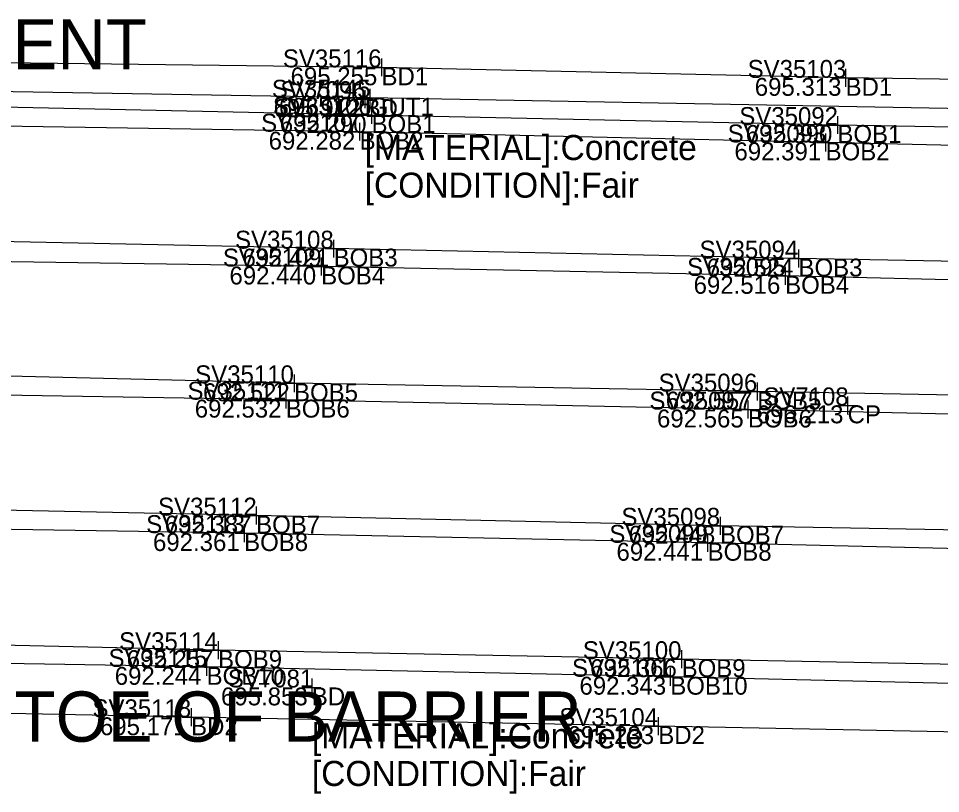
# Model space of a CAD drawing. Extents: x 1660019 to 1662995, y 619975 to 620342.
# Drawn here: x 1661296.6 to 1661348, y 620210.2 to 620253.4 of the extents above; entities that cross this region are included whole.
import ezdxf

# ---------------------------------------------------------------- set-up
doc = ezdxf.new("R2010")
doc.units = 0
for name, color, linetype in [('BR_X_Rail_Object', 7, 'Continuous'), ('BR_X_SV_Bottom_of_Beam', 7, 'Continuous'), ('BR_X_SV_Bottom_of_Beam_Text', 7, 'Continuous'), ('BR_X_SV_Deck_Top', 7, 'Continuous'), ('BR_X_SV_Deck_Top_Text', 7, 'Continuous'), ('PV_X_Curb', 7, 'Continuous'), ('RD_P_GR_Lt', 7, 'Continuous'), ('RD_X_GR_Bar', 7, 'Continuous'), ('RD_X_Wall', 7, 'Continuous'), ('SC_Scratch6', 7, 'Continuous'), ('SV_X_Text', 7, 'Continuous')]:
    doc.layers.add(name, color=color, linetype=linetype)

msp = doc.modelspace()

# ---------------------------------------------------------------- linework, layer by layer
at = {"layer": 'BR_X_SV_Bottom_of_Beam'}
for points in [[(1661523.404, 620243.849), (1661497.415, 620244.383), (1661471.694, 620244.95), (1661445.773, 620245.45), (1661419.903, 620245.974), (1661394.009, 620246.51), (1661368.147, 620247.032), (1661342.287, 620247.488), (1661316.311, 620248.045), (1661290.557, 620248.602), (1661264.648, 620249.031), (1661238.6, 620249.579)], [(1661517.582, 620243.008), (1661496.897, 620243.44), (1661470.919, 620243.838), (1661445.09, 620244.441), (1661419.147, 620244.946), (1661393.26, 620245.417), (1661367.358, 620245.921), (1661341.629, 620246.518), (1661315.646, 620247.115), (1661289.746, 620247.518), (1661264.383, 620248.322), (1661238.204, 620248.614)], [(1661521.265, 620236.365), (1661495.332, 620236.959), (1661469.491, 620237.512), (1661443.572, 620237.996), (1661417.708, 620238.508), (1661391.884, 620239.08), (1661365.994, 620239.561), (1661340.119, 620240.034), (1661314.197, 620240.589), (1661288.354, 620241.145), (1661262.476, 620241.611), (1661236.623, 620242.15)], [(1661520.605, 620235.452), (1661494.63, 620235.975), (1661468.71, 620236.383), (1661442.944, 620236.996), (1661417.103, 620237.514), (1661391.103, 620237.982), (1661365.202, 620238.448), (1661339.374, 620239.07), (1661313.502, 620239.591), (1661287.59, 620239.99), (1661261.723, 620240.632), (1661235.908, 620241.144)], [(1661519.081, 620228.953), (1661493.234, 620229.438), (1661467.368, 620230.031), (1661441.422, 620230.57), (1661415.6, 620231.071), (1661389.731, 620231.651), (1661363.823, 620232.132), (1661337.817, 620232.613), (1661311.988, 620233.076), (1661286.183, 620233.721), (1661260.328, 620234.129), (1661234.382, 620234.656)], [(1661518.51, 620227.977), (1661492.527, 620228.475), (1661466.56, 620228.954), (1661440.742, 620229.56), (1661414.823, 620230.069), (1661388.938, 620230.522), (1661363.07, 620231.021), (1661337.298, 620231.612), (1661311.527, 620232.162), (1661285.446, 620232.587), (1661259.588, 620233.138), (1661233.669, 620233.674)], [(1661516.938, 620221.488), (1661491.079, 620222.019), (1661465.187, 620222.58), (1661439.251, 620223.092), (1661413.441, 620223.61), (1661387.584, 620224.174), (1661361.703, 620224.657), (1661335.742, 620225.126), (1661309.876, 620225.693), (1661284.015, 620226.238), (1661258.155, 620226.696), (1661232.1, 620227.235)], [(1661516.255, 620220.542), (1661490.624, 620220.907), (1661464.53, 620221.454), (1661438.64, 620222.101), (1661412.707, 620222.613), (1661386.76, 620223.066), (1661360.949, 620223.557), (1661335.05, 620224.176), (1661309.206, 620224.717), (1661283.267, 620225.126), (1661257.537, 620225.694), (1661231.605, 620226.262)], [(1661514.756, 620214.059), (1661488.914, 620214.555), (1661463.017, 620215.148), (1661437.126, 620215.616), (1661411.256, 620216.167), (1661385.428, 620216.691), (1661359.541, 620217.184), (1661333.602, 620217.682), (1661307.754, 620218.183), (1661281.891, 620218.773), (1661255.858, 620219.275), (1661229.67, 620219.799)], [(1661514.073, 620213.08), (1661488.21, 620213.597), (1661462.263, 620214.044), (1661436.515, 620214.643), (1661410.516, 620215.165), (1661384.602, 620215.601), (1661358.815, 620216.084), (1661332.968, 620216.701), (1661307.113, 620217.251), (1661281.101, 620217.691), (1661255.319, 620218.266), (1661229.464, 620218.851)]]:
    msp.add_lwpolyline(points, dxfattribs=at)
at = {"layer": 'BR_X_SV_Deck_Top'}
for points in [[(1661524.154, 620246.519), (1661498.291, 620247.067), (1661472.426, 620247.598), (1661446.524, 620248.074), (1661420.55, 620248.604), (1661394.772, 620249.021), (1661368.927, 620249.743), (1661342.743, 620250.117), (1661316.866, 620250.706), (1661291.246, 620251.013), (1661265.132, 620251.796)], [(1661513.529, 620210.295), (1661487.664, 620211.099), (1661461.66, 620211.354), (1661435.632, 620211.885), (1661409.962, 620212.424), (1661383.838, 620212.928), (1661332.298, 620213.947), (1661306.248, 620214.439), (1661280.429, 620214.969), (1661254.732, 620215.771)]]:
    msp.add_lwpolyline(points, dxfattribs=at)
at = {"layer": 'PV_X_Curb'}
msp.add_lwpolyline([(1661523.342, 620245.121), (1661471.566, 620246.113), (1661445.996, 620246.597), (1661316.22, 620249.01), (1661290.79, 620249.439), (1661264.952, 620250.247), (1661238.714, 620250.79)], dxfattribs=at)
at = {"layer": 'RD_P_GR_Lt'}
for p, q in [((1661316.866, 620251.206), (1661316.866, 620250.206)), ((1661316.366, 620250.706), (1661317.366, 620250.706)), ((1661316.866, 620250.706), (1661316.866, 620250.706)), ((1661342.743, 620250.617), (1661342.743, 620249.617)), ((1661342.243, 620250.117), (1661343.243, 620250.117)), ((1661342.743, 620250.117), (1661342.743, 620250.117)), ((1661315.927, 620249.432), (1661315.927, 620248.432)), ((1661316.22, 620249.51), (1661316.22, 620248.51)), ((1661315.427, 620248.932), (1661316.427, 620248.932)), ((1661315.72, 620249.01), (1661316.72, 620249.01)), ((1661315.927, 620248.932), (1661315.927, 620248.932)), ((1661316.22, 620249.01), (1661316.22, 620249.01)), ((1661316.311, 620248.545), (1661316.311, 620247.545)), ((1661315.811, 620248.045), (1661316.811, 620248.045)), ((1661316.311, 620248.045), (1661316.311, 620248.045)), ((1661342.287, 620247.988), (1661342.287, 620246.988)), ((1661315.646, 620247.615), (1661315.646, 620246.615)), ((1661341.787, 620247.488), (1661342.787, 620247.488)), ((1661342.287, 620247.488), (1661342.287, 620247.488)), ((1661315.146, 620247.115), (1661316.146, 620247.115)), ((1661315.646, 620247.115), (1661315.646, 620247.115)), ((1661341.629, 620247.018), (1661341.629, 620246.018)), ((1661341.129, 620246.518), (1661342.129, 620246.518)), ((1661341.629, 620246.518), (1661341.629, 620246.518)), ((1661314.197, 620241.089), (1661314.197, 620240.089)), ((1661313.697, 620240.589), (1661314.697, 620240.589)), ((1661314.197, 620240.589), (1661314.197, 620240.589)), ((1661340.119, 620240.534), (1661340.119, 620239.534)), ((1661313.502, 620240.091), (1661313.502, 620239.091)), ((1661339.619, 620240.034), (1661340.619, 620240.034)), ((1661340.119, 620240.034), (1661340.119, 620240.034)), ((1661313.002, 620239.591), (1661314.002, 620239.591)), ((1661313.502, 620239.591), (1661313.502, 620239.591)), ((1661339.374, 620239.57), (1661339.374, 620238.57)), ((1661338.874, 620239.07), (1661339.874, 620239.07)), ((1661339.374, 620239.07), (1661339.374, 620239.07)), ((1661311.988, 620233.576), (1661311.988, 620232.576)), ((1661311.488, 620233.076), (1661312.488, 620233.076)), ((1661311.988, 620233.076), (1661311.988, 620233.076)), ((1661337.817, 620233.113), (1661337.817, 620232.113)), ((1661311.527, 620232.662), (1661311.527, 620231.662)), ((1661337.317, 620232.613), (1661338.317, 620232.613)), ((1661337.817, 620232.613), (1661337.817, 620232.613)), ((1661311.027, 620232.162), (1661312.027, 620232.162)), ((1661311.527, 620232.162), (1661311.527, 620232.162)), ((1661337.298, 620232.112), (1661337.298, 620231.112)), ((1661342.854, 620232.344), (1661342.854, 620231.344)), ((1661336.798, 620231.612), (1661337.798, 620231.612)), ((1661337.298, 620231.612), (1661337.298, 620231.612)), ((1661342.354, 620231.844), (1661343.354, 620231.844)), ((1661342.854, 620231.844), (1661342.854, 620231.844)), ((1661309.876, 620226.193), (1661309.876, 620225.193)), ((1661309.376, 620225.693), (1661310.376, 620225.693)), ((1661309.876, 620225.693), (1661309.876, 620225.693)), ((1661335.742, 620225.626), (1661335.742, 620224.626)), ((1661308.706, 620224.717), (1661309.706, 620224.717)), ((1661309.206, 620225.217), (1661309.206, 620224.217)), ((1661309.206, 620224.717), (1661309.206, 620224.717)), ((1661335.242, 620225.126), (1661336.242, 620225.126)), ((1661335.742, 620225.126), (1661335.742, 620225.126)), ((1661335.05, 620224.676), (1661335.05, 620223.676)), ((1661334.55, 620224.176), (1661335.55, 620224.176)), ((1661335.05, 620224.176), (1661335.05, 620224.176)), ((1661307.754, 620218.683), (1661307.754, 620217.683)), ((1661307.254, 620218.183), (1661308.254, 620218.183)), ((1661307.754, 620218.183), (1661307.754, 620218.183)), ((1661333.602, 620218.182), (1661333.602, 620217.182)), ((1661307.113, 620217.751), (1661307.113, 620216.751)), ((1661333.102, 620217.682), (1661334.102, 620217.682)), ((1661333.602, 620217.682), (1661333.602, 620217.682)), ((1661306.613, 620217.251), (1661307.613, 620217.251)), ((1661307.113, 620217.251), (1661307.113, 620217.251)), ((1661332.968, 620217.201), (1661332.968, 620216.201)), ((1661312.981, 620216.605), (1661312.981, 620215.605)), ((1661332.468, 620216.701), (1661333.468, 620216.701)), ((1661332.968, 620216.701), (1661332.968, 620216.701)), ((1661312.481, 620216.105), (1661313.481, 620216.105)), ((1661312.981, 620216.105), (1661312.981, 620216.105)), ((1661306.248, 620214.939), (1661306.248, 620213.939)), ((1661305.748, 620214.439), (1661306.748, 620214.439)), ((1661306.248, 620214.439), (1661306.248, 620214.439)), ((1661332.298, 620214.447), (1661332.298, 620213.447)), ((1661331.798, 620213.947), (1661332.798, 620213.947)), ((1661332.298, 620213.947), (1661332.298, 620213.947))]:
    msp.add_line(p, q, dxfattribs=at)

# ---------------------------------------------------------------- texts
at = {"layer": 'BR_X_Rail_Object'}
for s, p in [('GUT1', (1661316.22, 620248.01)), ('CP', (1661342.854, 620230.844))]:
    msp.add_text(s, height=1, dxfattribs=at).set_placement(p)
at = {"layer": 'BR_X_SV_Bottom_of_Beam_Text'}
for s, p in [('SV35106', (1661310.811, 620248.045)), ('SV35092', (1661336.818, 620247.488)), ('SV35107', (1661310.154, 620247.115)), ('692.290', (1661311.197, 620247.045)), ('BOB1', (1661316.311, 620247.045)), ('SV35093', (1661336.169, 620246.518)), ('692.390', (1661337.173, 620246.488)), ('BOB1', (1661342.287, 620246.488)), ('692.282', (1661310.573, 620246.115)), ('BOB2', (1661315.646, 620246.115)), ('692.391', (1661336.547, 620245.518)), ('BOB2', (1661341.629, 620245.518)), ('SV35108', (1661308.7, 620240.589)), ('SV35094', (1661334.601, 620240.034)), ('SV35109', (1661308.022, 620239.591)), ('692.421', (1661309.115, 620239.589)), ('BOB3', (1661314.197, 620239.589)), ('SV35095', (1661333.907, 620239.07)), ('692.524', (1661334.997, 620239.034)), ('BOB3', (1661340.119, 620239.034)), ('692.440', (1661308.388, 620238.591)), ('BOB4', (1661313.502, 620238.591)), ('692.516', (1661334.27, 620238.07)), ('BOB4', (1661339.374, 620238.07)), ('SV35110', (1661306.478, 620233.076)), ('SV35096', (1661332.317, 620232.613)), ('SV35111', (1661306.049, 620232.162)), ('692.522', (1661306.915, 620232.076)), ('BOB5', (1661311.988, 620232.076)), ('SV35097', (1661331.806, 620231.612)), ('692.557', (1661332.721, 620231.613)), ('BOB5', (1661337.817, 620231.613)), ('692.532', (1661306.454, 620231.162)), ('BOB6', (1661311.527, 620231.162)), ('692.565', (1661332.228, 620230.612)), ('BOB6', (1661337.298, 620230.612)), ('SV35112', (1661304.407, 620225.693)), ('SV35098', (1661330.245, 620225.126)), ('SV35113', (1661303.746, 620224.717)), ('692.387', (1661304.78, 620224.693)), ('BOB7', (1661309.876, 620224.693)), ('692.361', (1661304.124, 620223.717)), ('BOB8', (1661309.206, 620223.717)), ('SV35099', (1661329.57, 620224.176)), ('692.448', (1661330.642, 620224.126)), ('BOB7', (1661335.742, 620224.126)), ('692.441', (1661329.968, 620223.176)), ('BOB8', (1661335.05, 620223.176)), ('SV35114', (1661302.236, 620218.183)), ('SV35100', (1661328.092, 620217.682)), ('SV35115', (1661301.646, 620217.251)), ('692.257', (1661302.658, 620217.183)), ('BOB9', (1661307.754, 620217.183)), ('SV35101', (1661327.49, 620216.701)), ('692.366', (1661328.498, 620216.682)), ('BOB9', (1661333.602, 620216.682)), ('692.244', (1661301.991, 620216.251)), ('BOB10', (1661307.113, 620216.251)), ('692.343', (1661327.904, 620215.701)), ('BOB10', (1661332.968, 620215.701))]:
    msp.add_text(s, height=1, dxfattribs=at).set_placement(p)
at = {"layer": 'BR_X_SV_Deck_Top_Text'}
for s, p in [('SV35116', (1661311.366, 620250.706)), ('SV35103', (1661337.283, 620250.117)), ('695.255', (1661311.796, 620249.706)), ('BD1', (1661316.866, 620249.706)), ('SV7096', (1661311.225, 620248.932)), ('695.313', (1661337.679, 620249.117)), ('BD1', (1661342.743, 620249.117)), ('695.912', (1661310.854, 620247.932)), ('BD', (1661315.927, 620247.932)), ('SV7081', (1661308.301, 620216.105)), ('695.853', (1661307.917, 620215.105)), ('BD', (1661312.981, 620215.105)), ('SV35118', (1661300.751, 620214.439)), ('SV35104', (1661326.78, 620213.947)), ('695.171', (1661301.166, 620213.439)), ('BD2', (1661306.248, 620213.439)), ('695.233', (1661327.234, 620212.947)), ('BD2', (1661332.298, 620212.947))]:
    msp.add_text(s, height=1, dxfattribs=at).set_placement(p)
at = {"layer": 'RD_X_GR_Bar'}
for s, p in [('696.022', (1661311.147, 620248.01)), ('696.213', (1661337.79, 620230.844))]:
    msp.add_text(s, height=1, dxfattribs=at).set_placement(p)
at = {"layer": 'RD_X_Wall'}
for s, p in [('SV35145', (1661310.753, 620249.01)), ('SV7108', (1661338.155, 620231.844))]:
    msp.add_text(s, height=1, dxfattribs=at).set_placement(p)
at = {"layer": 'SC_Scratch6'}
for s, p in [('MISSING OUTLINE OF ABUTMENT', (1661242.831, 620250.594)), ('MISSING TOE OF BARRIER', (1661279.557, 620213.079))]:
    msp.add_text(s, height=2.79999, dxfattribs=at).set_placement(p)
at = {"layer": 'SV_X_Text'}
for s, p in [('[MATERIAL]:Concrete', (1661315.927, 620245.532)), ('[CONDITION]:Fair', (1661315.927, 620243.432)), ('[MATERIAL]:Concrete', (1661312.981, 620212.705)), ('[CONDITION]:Fair', (1661312.981, 620210.605))]:
    msp.add_text(s, height=1.4, dxfattribs=at).set_placement(p)

doc.saveas('drawing.dxf')
